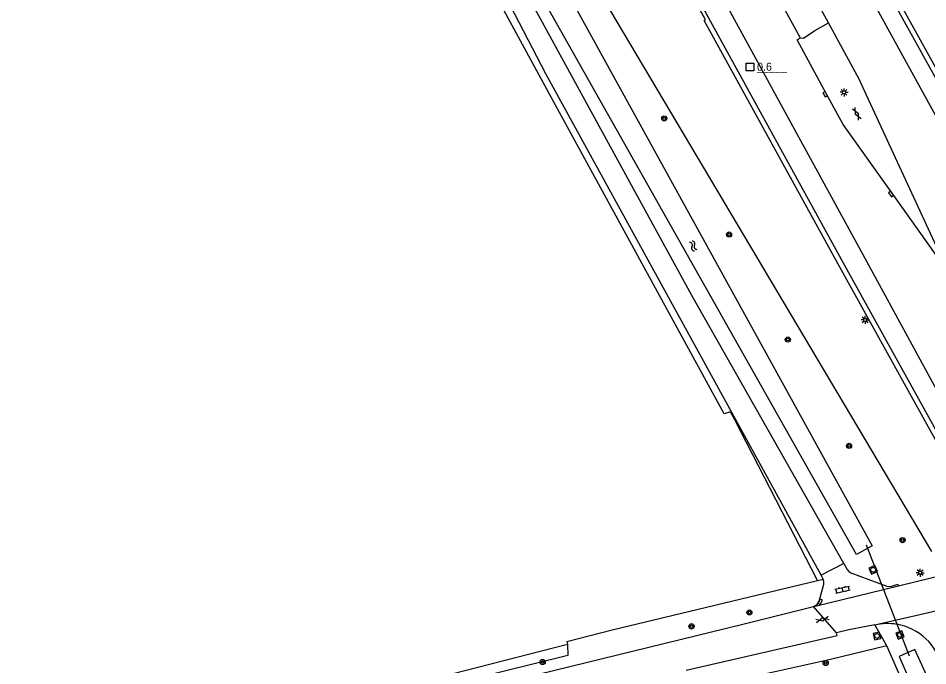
# Model space of a CAD drawing. Extents: x 135999 to 138000, y 396000 to 398501.
# Drawn here: x 137216.3 to 137358.4, y 397206.2 to 397307.4 of the extents above; entities that cross this region are included whole.
import ezdxf

# ---------------------------------------------------------------- set-up
doc = ezdxf.new("R2010")
doc.units = 0
for name, color, linetype in [('gg-afsc-draadraster', 7, 'Continuous'), ('gg-afsc-hekwerk', 7, 'Continuous'), ('gg-knt-bovenkant onderkant talud', 7, 'Continuous'), ('gg-knt-onverhard', 7, 'Continuous'), ('gg-knt-verharding', 7, 'Continuous'), ('gg-kntw-bovenkant insteek waterloop', 7, 'Continuous'), ('gg-kntw-greppel-droge sloot', 7, 'Continuous'), ('gg-kwrk-duiker nz buis', 7, 'Continuous'), ('gg-kwrk-kunstwerk', 7, 'Continuous'), ('gt-anno-nummer hm paal', 7, 'Continuous'), ('gt-grn-groengrens', 7, 'Continuous'), ('gt-grn-weggrens', 7, 'Continuous'), ('gt-symb-boom', 7, 'Continuous'), ('gt-symb-gesloten verharding', 7, 'Continuous'), ('gt-symb-hm paal', 7, 'Continuous'), ('gt-symb-klinker verharding', 7, 'Continuous'), ('gt-symb-kolk', 7, 'Continuous'), ('gt-symb-lichtmast', 7, 'Continuous'), ('gt-symb-rioolschacht', 7, 'Continuous'), ('gt-symb-watersymbool', 7, 'Continuous')]:
    doc.layers.add(name, color=color, linetype=linetype)

# ---------------------------------------------------------------- blocks, each defined once
blk = doc.blocks.new('gt0-KL1')
at = {"layer": 'gt-symb-klinker verharding'}
for p, q in [((-1.15, 0.3), (1.15, 0.3)), ((-1, -0.3), (-1, 0.3)), ((-0.5, 0.3), (-0.5, 0.45)), ((0, -0.3), (0, 0.3)), ((0.5, 0.3), (0.5, 0.45)), ((1, -0.3), (1, 0.3)), ((-1.15, -0.3), (1.15, -0.3)), ((-0.5, -0.45), (-0.5, -0.3)), ((0.5, -0.45), (0.5, -0.3))]:
    blk.add_line(p, q, dxfattribs=at)
blk = doc.blocks.new('gt0-LMAST')
at = {"layer": 'gt-symb-lichtmast'}
for p, q in [((-0.18, 0.17), (-0.45, 0.44)), ((-0.01, 0.25), (-0.01, 0.62)), ((0.17, 0.17), (0.44, 0.44)), ((-0.26, 0), (-0.63, 0)), ((-0.18, -0.18), (-0.45, -0.45)), ((-0.01, -0.25), (-0.01, -0.63)), ((0.44, -0.45), (0.17, -0.18)), ((0.24, 0), (0.62, 0))]:
    blk.add_line(p, q, dxfattribs=at)
blk.add_circle((-0.01, 0), 0.25, dxfattribs=at)
blk = doc.blocks.new('gt0-RS')
at = {"layer": 'gt-symb-rioolschacht'}
blk.add_lwpolyline([(-0.5, -0.5), (0.5, -0.5), (0.5, 0.5), (-0.5, 0.5)], close=True, dxfattribs=at)
blk.add_circle((0, 0), 0.375, dxfattribs=at)
blk = doc.blocks.new('gt0-BOOM')
at = {"layer": 'gt-symb-boom'}
for radius in [0.4, 0.2]:
    blk.add_circle((0, 0), radius, dxfattribs=at)
blk = doc.blocks.new('gt0-WA')
at = {"layer": 'gt-symb-watersymbool'}
for centre, start, end in [((-0.32, 0.02), 28.0725, 151.9275), ((0.43, 0.42), 208.0725, 331.9275), ((-0.32, -0.43), 28.0725, 151.9275), ((0.43, -0.03), 208.0725, 331.9275)]:
    blk.add_arc(centre, 0.425, start, end, dxfattribs=at)
blk = doc.blocks.new('gt0-KOLK')
at = {"layer": 'gt-symb-kolk'}
blk.add_lwpolyline([(0, 0), (0.38, 0), (0.38, 0.4), (-0.38, 0.4), (-0.38, 0), (0, 0)], dxfattribs=at)
blk = doc.blocks.new('gt0-GESVH1')
at = {"layer": 'gt-symb-gesloten verharding'}
for p, q in [((-0.99, -0.26), (0.01, 0.24)), ((0.01, -0.26), (-0.99, 0.24)), ((0.01, 0.24), (1.01, -0.26)), ((1.01, 0.24), (0.01, -0.26))]:
    blk.add_line(p, q, dxfattribs=at)
blk = doc.blocks.new('gt0-HMpaal')
at = {"layer": 'gt-symb-hm paal'}
blk.add_lwpolyline([(-0.6, 0.6), (0.6, 0.6), (0.6, -0.6), (-0.6, -0.6)], close=True, dxfattribs=at)

msp = doc.modelspace()

# ---------------------------------------------------------------- linework, layer by layer
at = {"layer": 'gg-afsc-draadraster'}
msp.add_lwpolyline([(137341.16, 397219.53), (137328.26, 397244.62), (137327.56, 397245.91), (137326.6, 397245.57), (137299.92, 397294.35), (137266.38, 397356.14), (137249.47, 397388.66), (137226.73, 397433.28), (137216.63, 397452.73)], dxfattribs=at)
at = {"layer": 'gg-afsc-hekwerk'}
for p, q in [((137351.99, 397209.36), (137343.21, 397207.19)), ((137351.99, 397209.36), (137343.21, 397207.19)), ((137368.29, 397172.65), (137351.99, 397209.36)), ((137368.29, 397172.65), (137351.99, 397209.36))]:
    msp.add_line(p, q, dxfattribs=at)
at = {"layer": 'gg-knt-bovenkant onderkant talud'}
msp.add_lwpolyline([(137228.34, 397465.26), (137251.14, 397419.03), (137302.43, 397319.31), (137358.97, 397224.09)], dxfattribs=at)
at = {"layer": 'gg-knt-onverhard'}
for points in [[(137345.3, 397222.2), (137321.56, 397264.05), (137287.02, 397327.2), (137250.17, 397399.55), (137224.44, 397452.06), (137220.38, 397461.3)], [(137341.74, 397220.36), (137298.76, 397298.65), (137251.61, 397389.43), (137216.34, 397459.36)]]:
    msp.add_lwpolyline(points, dxfattribs=at)
at = {"layer": 'gg-knt-verharding'}
for p, q in [((137345.3, 397222.2), (137341.74, 397220.36)), ((137353.81, 397218.71), (137368.09, 397222.24)), ((137342.08, 397219.75), (137341.74, 397220.36))]:
    msp.add_line(p, q, dxfattribs=at)
for points in [[(137264.57, 397473.59), (137269.15, 397464.35), (137277.91, 397446.86), (137286.71, 397429.45), (137295.65, 397412.02), (137304.58, 397394.71), (137313.57, 397377.45), (137322.67, 397360.3), (137331.82, 397343.15), (137341.1, 397325.93), (137350.45, 397308.81), (137359.85, 397291.69), (137369.31, 397274.66), (137378.89, 397257.58), (137382.92, 397250.48)], [(137242.92, 397471.78), (137250.76, 397455.87), (137259.81, 397437.64), (137268.21, 397421.08), (137277.64, 397402.67), (137287.47, 397383.71), (137295.92, 397367.54), (137304.87, 397350.65), (137327.83, 397307.78), (137347.92, 397271.05), (137369.83, 397230.77)], [(137342.89, 397306.63), (137327.43, 397334.92), (137316.88, 397354.69), (137306.62, 397374), (137297.77, 397390.93), (137288.67, 397408.7), (137279.8, 397425.87), (137270.97, 397443.46), (137260.43, 397464.5), (137257.53, 397470.36)], [(137252.82, 397468.96), (137257.67, 397459.15), (137266.37, 397441.71), (137275.18, 397424.27), (137284.24, 397406.56), (137293.27, 397389.07), (137302.52, 397370.72), (137311.4, 397354.61), (137320.61, 397337.32), (137329.86, 397320.06), (137338.45, 397304.31)], [(137338.45, 397304.31), (137338.96, 397304.24), (137340.74, 397305.43), (137342.89, 397306.63)], [(137380.61, 397233.25), (137360.1, 397270.91), (137348.49, 397296), (137347.67, 397297.82), (137342.89, 397306.63)], [(137379.95, 397233.1), (137359.62, 397270.51), (137352.82, 397280.02), (137345.2, 397290.74), (137342.53, 397295.59), (137337.99, 397304), (137338.45, 397304.31)], [(137345.3, 397222.2), (137345.78, 397221.24), (137346.04, 397220.94), (137346.38, 397220.75), (137352.01, 397218.68), (137352.4, 397218.61), (137352.8, 397218.67), (137353.74, 397218.95), (137353.81, 397218.71)], [(137340.55, 397215.48), (137341.11, 397215.79), (137341.41, 397216.32), (137342.14, 397218.98), (137342.17, 397219.37), (137342.08, 397219.75)], [(137340.55, 397215.48), (137340.8, 397215.54), (137353.81, 397218.71)], [(137261.51, 397197.06), (137261.95, 397197.28), (137268.62, 397198.3), (137269.06, 397198.18), (137275.49, 397199.51), (137329.49, 397212.72), (137340.55, 397215.48)], [(137350.13, 397212.6), (137346.06, 397211.84), (137344.12, 397211.36)], [(137320.64, 397205.52), (137344.23, 397210.95), (137344.12, 397211.36)]]:
    msp.add_lwpolyline(points, dxfattribs=at)
for centre, radius, start, end in [((137352.1, 397204.06), 8.76, 80.3978, 102.9755), ((137352.1, 397204.09), 8.74, 13.0168, 80.3629)]:
    msp.add_arc(centre, radius, start, end, dxfattribs=at)
at = {"layer": 'gg-kntw-bovenkant insteek waterloop'}
for points in [[(137226.12, 397452.24), (137229.05, 397453.69), (137246.87, 397417.56), (137299.11, 397316.82), (137349.73, 397224.98), (137347.26, 397223.6), (137294.26, 397317.51), (137243.92, 397416.17), (137226.12, 397452.24)], [(137366.61, 397178.7), (137369.26, 397180.49), (137356.37, 397208.76), (137353.94, 397207.7), (137366.61, 397178.7)]]:
    msp.add_lwpolyline(points, dxfattribs=at)
at = {"layer": 'gg-kntw-greppel-droge sloot'}
msp.add_line((137267.7, 397200.82), (137302.15, 397209.58), dxfattribs=at)
msp.add_lwpolyline([(137302.15, 397209.58), (137302.17, 397207.81), (137276.1, 397201.36), (137271.99, 397200.25), (137268.05, 397199.52), (137267.7, 397200.82)], dxfattribs=at)
at = {"layer": 'gg-kwrk-duiker nz buis'}
msp.add_line((137348.76, 397225.1), (137355.47, 397207.78), dxfattribs=at)
at = {"layer": 'gg-kwrk-kunstwerk'}
for points in [[(137390.18, 397243.42), (137371.67, 397276.28), (137352.89, 397310.23), (137325.52, 397361.15), (137304.63, 397400.81)], [(137394.56, 397237.45), (137390.86, 397243.83), (137372.36, 397276.69), (137353.58, 397310.63), (137326.21, 397361.56), (137305.33, 397401.19)], [(137365.94, 397230.6), (137364.24, 397233.57), (137364.06, 397233.47), (137344.41, 397268.95), (137323.49, 397306.99), (137323.66, 397307.09), (137322.23, 397309.75)], [(137366.92, 397230.1), (137364.76, 397233.87), (137344.99, 397269.55), (137324.19, 397307.37), (137322.75, 397310.05)]]:
    msp.add_lwpolyline(points, dxfattribs=at)
at = {"layer": 'gt-grn-groengrens'}
for p, q in [((137309.08, 397211.82), (137341.16, 397219.53)), ((137341.16, 397219.53), (137342.08, 397219.75)), ((137302.04, 397210), (137309.08, 397211.82)), ((137351.99, 397209.36), (137350.13, 397212.6)), ((137302.04, 397210), (137302.15, 397209.58)), ((137343.21, 397207.19), (137318.88, 397201.85))]:
    msp.add_line(p, q, dxfattribs=at)
at = {"layer": 'gt-grn-weggrens'}
for p, q in [((137350.13, 397212.6), (137369.22, 397217.08)), ((137344.12, 397211.36), (137340.55, 397215.48))]:
    msp.add_line(p, q, dxfattribs=at)

# ---------------------------------------------------------------- block references
at = {"layer": 'gt-symb-boom'}
for p in [(137317.24, 397291.72), (137327.36, 397273.58), (137336.54, 397257.18), (137346.1, 397240.57), (137354.46, 397225.85), (137330.54, 397214.55), (137321.5, 397212.39), (137298.25, 397206.82), (137342.45, 397206.66)]:
    msp.add_blockref('gt0-BOOM', p, dxfattribs=at)
at = {"layer": 'gt-symb-gesloten verharding'}
for p, rotation in [((137347.3, 397292.42), 117.25687178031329), ((137341.95, 397213.45), -165.99155651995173)]:
    msp.add_blockref('gt0-GESVH1', p, dxfattribs=dict(at, rotation=rotation))
at = {"layer": 'gt-symb-hm paal'}
msp.add_blockref('gt0-HMpaal', (137330.65, 397299.76), dxfattribs=at)
at = {"layer": 'gt-symb-klinker verharding', "rotation": 12.410774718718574}
msp.add_blockref('gt0-KL1', (137345.09, 397218.13), dxfattribs=at)
at = {"layer": 'gt-symb-kolk'}
for p, rotation in [((137342.53, 397295.59), 118.87101789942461), ((137352.82, 397280.02), 125.59763149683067), ((137341.41, 397216.32), -118.40935852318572)]:
    msp.add_blockref('gt0-KOLK', p, dxfattribs=dict(at, rotation=rotation))
at = {"layer": 'gt-symb-lichtmast'}
for p in [(137345.32, 397295.79), (137348.62, 397260.24), (137357.21, 397220.76)]:
    msp.add_blockref('gt0-LMAST', p, dxfattribs=at)
at = {"layer": 'gt-symb-rioolschacht'}
for p, rotation in [((137349.87, 397221.21), -65.17685962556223), ((137350.46, 397210.89), -167.9372539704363), ((137354.05, 397211.05), -157.8474134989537)]:
    msp.add_blockref('gt0-RS', p, dxfattribs=dict(at, rotation=rotation))
at = {"layer": 'gt-symb-watersymbool', "rotation": 119.15481037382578}
msp.add_blockref('gt0-WA', (137321.79, 397271.75), dxfattribs=at)

# ---------------------------------------------------------------- texts
at = {"layer": 'gt-anno-nummer hm paal'}
msp.add_text('0.6', height=1.25, dxfattribs=at).set_placement((137331.73, 397299.16))
at = {"layer": 'gt-symb-hm paal'}
msp.add_text('_____', height=1.25, dxfattribs=at).set_placement((137331.73, 397299.16))

doc.saveas('drawing.dxf')
